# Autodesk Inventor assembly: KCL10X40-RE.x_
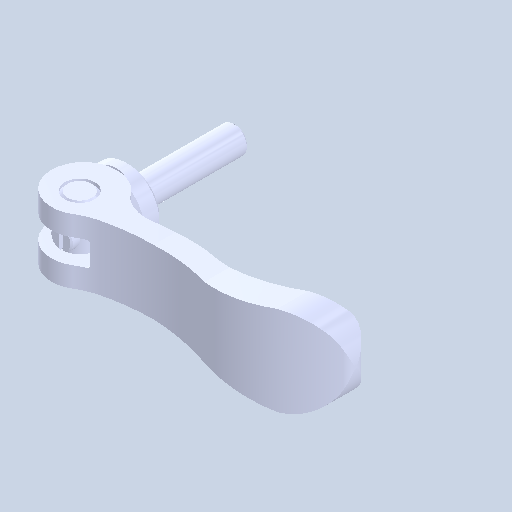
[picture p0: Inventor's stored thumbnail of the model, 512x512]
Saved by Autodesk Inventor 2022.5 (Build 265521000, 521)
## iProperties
Created: 2024-08
Part Number: KCL10X40-RE.x_
Document SubType Name: Assembly
Designer: ImaoCorp
Author: ImaoCorp
Sending System: SOLIDWORKS 2022-2022290
MC: AMD64
MC_MODEL: Intel64 Family 6 Model 60 Stepping 3, GenuineIntel
OS: Windows_NT
FRU: Parasolid Version 33.1, build 260,  4-25-2022
FORMAT: text
GUISE: transmit
KEY: FILEKCL10X40-RE.x_t
DATE: Thu Aug 29 10:51:07 2024
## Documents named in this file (5)
- Y:\5.更新分\2024年対応\1001_KCL\データ\kcl10x40-re\KCL10X40-RE.x_.iam
- Y:\5.更新分\2024年対応\1001_KCL\データ\kcl10x40-re\KCL10X40-RE_01.ipt
- Y:\5.更新分\2024年対応\1001_KCL\データ\kcl10x40-re\KCL10X40-RE_02.ipt
- Y:\5.更新分\2024年対応\1001_KCL\データ\kcl10x40-re\KCL10X40-RE_03.ipt
- Y:\5.更新分\2024年対応\1001_KCL\データ\kcl10x40-re\KCL10X40-RE_04.ipt
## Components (4 placed, 4 different names)
1. KCL10X40-RE_01
2. KCL10X40-RE_02
3. KCL10X40-RE_03
4. KCL10X40-RE_04
